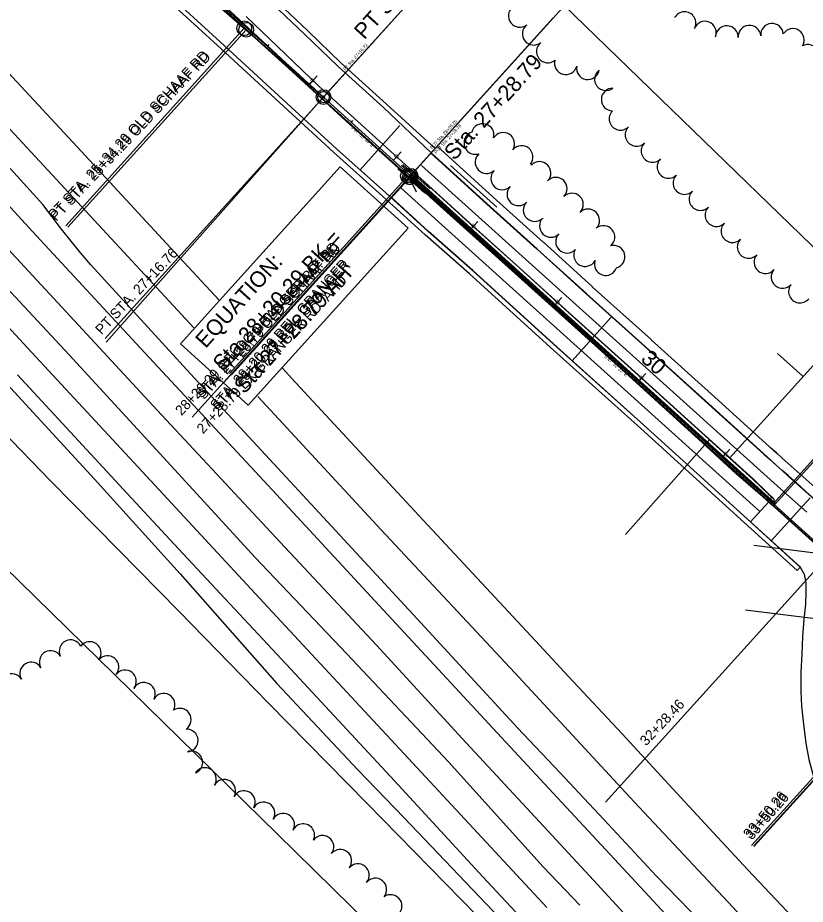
# Model space of a CAD drawing. Extents: x -25029 to 2274964, y -81170 to 687028.
# Drawn here: x -14288 to -13593, y -65698 to -64915 of the extents above; entities that cross this region are included whole.
import ezdxf

# ---------------------------------------------------------------- set-up
doc = ezdxf.new("R2010")
doc.units = 0
for name, color, linetype in [('81911BEA - RW_X_Fee_RW', 7, 'Continuous'), ('BD_P_Building', 7, 'Continuous'), ('BD_X_Canopy', 7, 'Continuous'), ('GE_X_CL_100', 7, 'Continuous'), ('GE_X_CL_20', 7, 'Continuous'), ('GE_X_CL_2000', 7, 'Continuous'), ('GK_Visualization', 7, 'Continuous'), ('INTERSTATE', 7, 'Continuous'), ('MT_P_Edge_Line', 7, 'Continuous'), ('MT_P_Lane_Line', 7, 'Continuous'), ('PM_P_Dotted_Line', 7, 'Continuous'), ('PM_P_Lane_Line', 7, 'Continuous'), ('PM_P_Stop_Line', 7, 'Continuous'), ('PV_X_EOP', 7, 'Continuous'), ('SC_Scratch18', 7, 'Continuous'), ('SC_Scratch19', 7, 'Continuous'), ('SC_Scratch20', 7, 'Continuous'), ('TREES', 7, 'Continuous')]:
    doc.layers.add(name, color=color, linetype=linetype)

msp = doc.modelspace()

# ---------------------------------------------------------------- linework, layer by layer
at = {"layer": '81911BEA - RW_X_Fee_RW'}
msp.add_line((-14059.38, -65635.72), (-13976.56, -65716.81), dxfattribs=at)
for points in [[(-13825.56, -64885.15), (-13539.44, -65162.6), (-13534.78, -65167.2)], [(-14520.82, -65183.95), (-14454.75, -65248.86), (-14188.94, -65508.88), (-14059.38, -65635.72)]]:
    msp.add_lwpolyline(points, dxfattribs=at)
at = {"layer": 'BD_P_Building'}
for p, q in [((-14154.25, -64867.25), (-14018.38, -64985.31)), ((-13937.46, -65056.39), (-13949.55, -65045.59)), ((-13948.22, -65044.94), (-13924.3, -65066.32)), ((-13952.89, -65048.79), (-13928.97, -65070.16)), ((-13939.45, -65058.63), (-13951.55, -65047.83)), ((-13942.8, -65056.23), (-13936.68, -65068.93)), ((-13940.93, -65059.47), (-13936.95, -65055.02))]:
    msp.add_line(p, q, dxfattribs=at)
at = {"layer": 'BD_X_Canopy'}
for p, q in [((-13941.57, -65054.73), (-13643.33, -64724.97)), ((-14018.38, -64985.31), (-13849.38, -64798.31)), ((-14018.38, -64985.31), (-14151.97, -64864.58)), ((-13621.39, -65344.31), (-13323.15, -65014.55)), ((-13620.28, -65345.31), (-13322.04, -65015.56))]:
    msp.add_line(p, q, dxfattribs=at)
msp.add_circle((-13621.39, -65344.31), 1.5, dxfattribs=at)
at = {"layer": 'GE_X_CL_100'}
for p, q in [((-14015.03, -64981.6), (-13855.1, -64804.64)), ((-13938.22, -65051.02), (-13815.56, -64915.39)), ((-14030.77, -64974.08), (-14024.04, -64966.68)), ((-14018.38, -64985.31), (-13941.57, -65054.73)), ((-13956.6, -65041.15), (-13949.89, -65033.73)), ((-14003.55, -65046.87), (-14110.15, -65164.82)), ((-14003.55, -65046.87), (-13943.59, -65101.06)), ((-13941.57, -65054.73), (-13570.99, -65389.89)), ((-13944.92, -65058.44), (-14106.73, -65237.46)), ((-13943.59, -65101.06), (-14084.79, -65257.29)), ((-13888.76, -65102.49), (-13882.05, -65095.08)), ((-13814.59, -65169.57), (-13807.88, -65162.15)), ((-14110.15, -65164.82), (-14144.74, -65203.1)), ((-14084.79, -65257.29), (-14144.74, -65203.1)), ((-13740.43, -65236.65), (-13733.72, -65229.23)), ((-13666.26, -65303.73), (-13659.55, -65296.31))]:
    msp.add_line(p, q, dxfattribs=at)
for centre in [(-14018.38, -64985.31), (-13941.57, -65054.73), (-13941.57, -65054.73)]:
    msp.add_circle(centre, 5, dxfattribs=at)
msp.add_arc((-10176.62, -60734.52), 5729.6, 224.293467, 227.893467, dxfattribs=at)
at = {"layer": 'GE_X_CL_20'}
for p, q in [((-14088.34, -64924.61), (-14245.86, -65098.99)), ((-14088.34, -64924.61), (-12952.92, -65950.25)), ((-14017.71, -64984.57), (-13973.41, -64935.55)), ((-14067.62, -64940.28), (-14066.26, -64938.82)), ((-14030.77, -64974.08), (-14029.43, -64972.6)), ((-14018.38, -64985.31), (-14211.12, -65198.57)), ((-14019.51, -64986.7), (-14210.21, -65201.8)), ((-14018.38, -64985.31), (-13941.57, -65054.73)), ((-13993.69, -65007.62), (-13992.35, -65006.14)), ((-13941.57, -65054.73), (-13893.63, -65001.68)), ((-13940.9, -65053.99), (-13893.83, -65001.94)), ((-13956.6, -65041.15), (-13955.26, -65039.66)), ((-13941.57, -65054.73), (-14134.32, -65267.99)), ((-13941.57, -65054.73), (-13570.99, -65389.89)), ((-13940.9, -65053.99), (-13619.61, -65344.57)), ((-13940.57, -65053.61), (-13619.27, -65344.2)), ((-13944, -65054.99), (-14101.52, -65229.37)), ((-13942.58, -65055.84), (-13621.28, -65346.43)), ((-13942.24, -65055.47), (-13620.95, -65346.06)), ((-13925.84, -65068.95), (-13924.5, -65067.47)), ((-13888.76, -65102.49), (-13887.42, -65101.01)), ((-13851.68, -65136.03), (-13850.33, -65134.55)), ((-13814.59, -65169.57), (-13813.25, -65168.09)), ((-13777.51, -65203.11), (-13776.17, -65201.63)), ((-13740.43, -65236.65), (-13739.09, -65235.17)), ((-13703.34, -65270.19), (-13702, -65268.7)), ((-13666.26, -65303.73), (-13664.92, -65302.24)), ((-13629.18, -65337.26), (-13627.84, -65335.78)), ((-13482.83, -65471.57), (-13640.35, -65645.95))]:
    msp.add_line(p, q, dxfattribs=at)
for centre, radius in [((-14088.34, -64924.61), 6.46), ((-14018.38, -64985.31), 6.46), ((-14018.38, -64985.31), 1), ((-13944, -65054.99), 6.46), ((-13941.57, -65054.73), 6.46), ((-13941.57, -65054.73), 1), ((-13941.57, -65054.73), 1)]:
    msp.add_circle(centre, radius, dxfattribs=at)
msp.add_arc((-10176.62, -60734.52), 5729.6, 224.293467, 227.893467, dxfattribs=at)
at = {"layer": 'GE_X_CL_2000'}
for points in [[(-14110.55, -65164.51), (-14149.64, -65122.46), (-14232.38, -65033.07), (-14331.2, -64926.77), (-14435.97, -64813.68), (-14530.31, -64711.32), (-14629.05, -64601.39), (-14673.9, -64549.55)], [(-14795.36, -64711.11), (-14635.94, -64875.63), (-14526.42, -64992.05), (-14414.68, -65111.67), (-14390.89, -65138.08), (-14315.48, -65219.95), (-14220.65, -65322.6), (-14145.05, -65406.13), (-14059.61, -65503.13), (-13988.06, -65579.37)], [(-13685.3, -65713.53), (-13724.7, -65672.87), (-13766.9, -65627.54), (-13809.75, -65581.55), (-13847.16, -65542.09), (-13935.82, -65445.94), (-14025.68, -65348.41), (-14135.75, -65229.65), (-14223.79, -65133.51), (-14232.65, -65123.17), (-14241.32, -65112.66), (-14249.78, -65101.99), (-14258.04, -65091.16), (-14266.09, -65080.18), (-14314.67, -65026.81)], [(-14322.7, -65127.56), (-14243.01, -65212.95), (-14159.51, -65303.7), (-14078.6, -65391.69), (-13997.83, -65476.78), (-13907.94, -65572.17), (-13824.32, -65664.78), (-13792.21, -65698.78)], [(-13594.69, -65719.67), (-13643.65, -65667.67), (-13677.75, -65630.88), (-13716.89, -65588.49), (-13754.7, -65547.56), (-13802.06, -65496.9), (-13831.12, -65465.44), (-13847.06, -65448.29), (-13934.21, -65354.59), (-14046.25, -65233.68), (-14054.73, -65224.56)], [(-13988.06, -65579.37), (-13947.34, -65621.46), (-13831.97, -65742.31)]]:
    msp.add_lwpolyline(points, dxfattribs=at)
at = {"layer": 'GK_Visualization'}
msp.add_line((-13941.57, -65054.73), (-13570.99, -65389.89), dxfattribs=at)
at = {"layer": 'INTERSTATE'}
msp.add_lwpolyline([(-12958.53, -66453.41), (-13014.05, -66394.29), (-13095.42, -66307.36), (-13172.46, -66224.15), (-13272.06, -66115.98), (-13357.27, -66023.46), (-13436.17, -65938.98), (-13503.35, -65866.48), (-13579.97, -65783.79), (-13657.09, -65700.57), (-13744.1, -65607.44), (-13849.48, -65493.49), (-13967.79, -65367.02), (-14065.28, -65261.64), (-14076.45, -65249.65)], dxfattribs=at)
at = {"layer": 'MT_P_Edge_Line'}
for p, q in [((-13923.59, -65034.84), (-13874.05, -65079.87)), ((-13938.68, -65051.53), (-13889.19, -65096.52)), ((-13874.14, -65079.79), (-13829.9, -65119.58)), ((-13889.19, -65096.52), (-13844.95, -65136.31)), ((-13829.82, -65119.66), (-13786.44, -65159.07)), ((-13844.95, -65136.31), (-13801.57, -65175.72)), ((-13786.54, -65158.97), (-13734.58, -65205.59)), ((-13801.57, -65175.72), (-13749.61, -65222.34)), ((-13734.55, -65205.62), (-13675.48, -65259.1)), ((-13749.61, -65222.34), (-13690.58, -65275.78)), ((-13675.48, -65259.1), (-13623.39, -65306.26)), ((-13690.58, -65275.78), (-13638.77, -65322.69)), ((-13653.94, -65317.86), (-13684.09, -65290.41)), ((-13624.44, -65343.42), (-13653.94, -65317.86)), ((-13638.76, -65322.69), (-13625.69, -65335.28)), ((-13625.7, -65335.28), (-13621.24, -65339.31))]:
    msp.add_line(p, q, dxfattribs=at)
for points in [[(-13684.09, -65290.41), (-13758.11, -65222.95), (-13843.55, -65145.98), (-13920.85, -65076.49), (-13943.14, -65056.46)], [(-13597.23, -65400.22), (-13653.64, -65349.08), (-13735.8, -65274.57), (-13812.47, -65205.68), (-13886.63, -65138.29), (-13925.73, -65103.9), (-13958.7, -65073.82)]]:
    msp.add_lwpolyline(points, dxfattribs=at)
msp.add_lwpolyline([(-13622.41, -65338.59), (-13625.64, -65342.19), (-13624.77, -65342.98), (-13624.17, -65343.48), (-13623.55, -65343.75), (-13623.03, -65343.85), (-13622.28, -65343.79), (-13621.69, -65343.59), (-13621.01, -65343.05), (-13620.66, -65342.46), (-13620.49, -65341.73), (-13620.44, -65341.22), (-13620.6, -65340.49), (-13621.12, -65339.76), (-13621.81, -65339.13)], close=True, dxfattribs=at)
msp.add_arc((-23716.78, -76654.7), 15187.62, 47.53132, 48.379524, dxfattribs=at)
at = {"layer": 'MT_P_Lane_Line'}
for p, q in [((-13614.85, -65331.12), (-13931.78, -65045.59)), ((-13633.01, -65351.28), (-13949.94, -65065.75))]:
    msp.add_line(p, q, dxfattribs=at)
at = {"layer": 'PM_P_Dotted_Line'}
msp.add_line((-13614.85, -65331.12), (-13591.77, -65351.92), dxfattribs=at)
at = {"layer": 'PM_P_Lane_Line'}
msp.add_line((-13906.15, -65045.79), (-13865.46, -65082.49), dxfattribs=at)
at = {"layer": 'PM_P_Stop_Line'}
for p, q in [((-14086.57, -64925.86), (-14244.05, -65100.27)), ((-14086.57, -64925.86), (-12950.89, -65951.2)), ((-13942.21, -65056.2), (-14099.68, -65230.62)), ((-13641.25, -65360.31), (-13625.38, -65342.81)), ((-13480.93, -65472.66), (-13638.4, -65647.08))]:
    msp.add_line(p, q, dxfattribs=at)
for centre in [(-14086.57, -64925.86), (-13942.21, -65056.2)]:
    msp.add_circle(centre, 6.46, dxfattribs=at)
at = {"layer": 'PV_X_EOP'}
for p, q in [((-14069.47, -64897), (-14035.09, -64929.81)), ((-14066.71, -64894.11), (-14032.33, -64926.92)), ((-14086.66, -64914.3), (-14051.95, -64947.43)), ((-14032.33, -64926.92), (-14002.75, -64955.29)), ((-14035.09, -64929.81), (-14005.48, -64958.21)), ((-14051.95, -64947.43), (-14022.12, -64976.04)), ((-14005.48, -64958.21), (-13965.52, -64994.5)), ((-14002.75, -64955.29), (-13962.83, -64991.54)), ((-14022.12, -64976.04), (-13981.92, -65012.55)), ((-13962.83, -64991.54), (-13919.81, -65030.66)), ((-13965.52, -64994.5), (-13923.42, -65034.66)), ((-13981.92, -65012.55), (-13939.88, -65050.77)), ((-13919.81, -65030.66), (-13917.12, -65027.69)), ((-13918.05, -65028.72), (-13868.5, -65073.77)), ((-13923.42, -65034.66), (-13873.88, -65079.69)), ((-13939.88, -65050.77), (-13889.35, -65096.7)), ((-13868.62, -65073.66), (-13824.38, -65113.45)), ((-13873.97, -65079.6), (-13829.73, -65119.39)), ((-13889.35, -65096.7), (-13845.11, -65136.49)), ((-13824.27, -65113.55), (-13780.89, -65152.96)), ((-13829.65, -65119.47), (-13786.27, -65158.88)), ((-13845.11, -65136.49), (-13801.73, -65175.9)), ((-13781.03, -65152.83), (-13729.07, -65199.45)), ((-13786.38, -65158.79), (-13734.42, -65205.41)), ((-13801.73, -65175.9), (-13749.77, -65222.52)), ((-13729.01, -65199.51), (-13669.94, -65252.99)), ((-13734.38, -65205.44), (-13675.31, -65258.92)), ((-13749.77, -65222.52), (-13690.74, -65275.96)), ((-13669.94, -65252.99), (-13617.85, -65300.15)), ((-13675.31, -65258.92), (-13623.22, -65306.08)), ((-13690.74, -65275.96), (-13638.93, -65322.87)), ((-13653.77, -65317.67), (-13683.92, -65290.22)), ((-13629.4, -65338.78), (-13653.77, -65317.67)), ((-13638.93, -65322.87), (-13625.86, -65335.46)), ((-13625.86, -65335.46), (-13621.41, -65339.49)), ((-13629.11, -65339.05), (-13624.57, -65343.16)), ((-13625.66, -65342.17), (-13622.41, -65338.59)), ((-13600.08, -65403.37), (-13597.39, -65400.4))]:
    msp.add_line(p, q, dxfattribs=at)
for points in [[(-13683.92, -65290.22), (-13757.94, -65222.76), (-13843.38, -65145.79), (-13920.68, -65076.3), (-13998.33, -65006.52), (-14079.27, -64932.04), (-14137.65, -64878.69), (-14184.85, -64835.65), (-14226.85, -64795.7), (-14257.17, -64766.5), (-14286.36, -64738.29)], [(-14132.84, -65189.05), (-14169.13, -65150.03), (-14235.6, -65078.13), (-14347.41, -64957.67), (-14462.09, -64833.67), (-14539.76, -64748.36)], [(-13600.08, -65403.37), (-13656.49, -65352.23), (-13738.64, -65277.72), (-13815.32, -65208.83), (-13889.46, -65141.46), (-13928.56, -65107.06), (-13966.15, -65072.77), (-14009.69, -65033.87), (-14112.38, -64939.55), (-14179.37, -64878.13), (-14309.3, -64760.68)], [(-13597.39, -65400.4), (-13653.8, -65349.26), (-13735.96, -65274.75), (-13812.63, -65205.86), (-13886.79, -65138.47), (-13925.89, -65104.08), (-13963.46, -65069.8), (-14007, -65030.9), (-14054.34, -64987.42), (-14109.67, -64936.6), (-14176.67, -64875.17), (-14306.43, -64757.88)], [(-14382.02, -64987.79), (-14275.46, -65104.01), (-14176.28, -65211.24), (-14063.55, -65332.3), (-13969.16, -65434.21), (-13850.1, -65562.87), (-13730.89, -65691.03), (-13604.15, -65828.11)], [(-14389.94, -65087.43), (-14279.9, -65206.41), (-14185.93, -65307.8), (-14067.43, -65435.51), (-13943.29, -65569.27), (-13821.19, -65700.9)], [(-13736.37, -65724.08), (-13779.99, -65676.71), (-13827.64, -65625.13), (-13895.81, -65551.53), (-13971.72, -65469.21), (-14056.68, -65378.22), (-14165.19, -65261.74), (-14300.6, -65115.56)], [(-13783.32, -65774.94), (-13877.59, -65673.83), (-13959.13, -65585.16), (-14051.34, -65485.91), (-14146.32, -65384.27), (-14195.3, -65331.45), (-14288.49, -65230.42)], [(-14302.52, -65279.75), (-14259.12, -65324.36), (-14199.82, -65384.68), (-14146.24, -65439.14), (-14067.33, -65520.01), (-13979.86, -65608.96), (-13869.11, -65721.96)], [(-13597.39, -65400.4), (-13593.92, -65406.41), (-13592.44, -65414.47), (-13592.51, -65423.21), (-13592.74, -65432.97), (-13594.29, -65446.66), (-13595.43, -65461.46), (-13596.08, -65476.76), (-13596.98, -65493.37), (-13596.86, -65510), (-13596.38, -65523.09), (-13594.66, -65539.04), (-13592.6, -65555.86), (-13589.75, -65570.09), (-13586.3, -65582.97), (-13582.48, -65598.89), (-13577.2, -65614.12), (-13570.86, -65630.39), (-13564.04, -65647.76), (-13556.86, -65661.88), (-13550.9, -65672.79), (-13538.17, -65693.91), (-13517.19, -65723.89)]]:
    msp.add_lwpolyline(points, dxfattribs=at)
for centre, radius, start, end in [((-23716.78, -76654.7), 15195.87, 47.53132, 48.379524), ((-23716.78, -76654.7), 15187.87, 47.53132, 48.379524), ((-13622.87, -65341.43), 2.42, 225.62221, 52.87799)]:
    msp.add_arc(centre, radius, start, end, dxfattribs=at)
at = {"layer": 'SC_Scratch18'}
for p, q in [((-14099.56, -65229.76), (-13942.04, -65055.38)), ((-13535.88, -65166.7), (-13659.89, -65303.98)), ((-13594.93, -65232.08), (-13617.55, -65211.65)), ((-13638.17, -65323.6), (-13659.89, -65303.98)), ((-13572.14, -65389.52), (-13638.48, -65381.14)), ((-13572.14, -65389.52), (-13769.32, -65607.82)), ((-13579.34, -65446.56), (-13645.68, -65438.18)), ((-13480.87, -65471.97), (-13638.39, -65646.35))]:
    msp.add_line(p, q, dxfattribs=at)
at = {"layer": 'SC_Scratch19'}
for p, q in [((-13986.04, -65049.64), (-13951.1, -65010.53)), ((-13798.95, -65218.16), (-13764.4, -65179.71)), ((-13623.16, -65377.04), (-13588.81, -65339.15))]:
    msp.add_line(p, q, dxfattribs=at)
at = {"layer": 'SC_Scratch20'}
msp.add_line((-13751.78, -65371.43), (-13677.26, -65287.37), dxfattribs=at)
at = {"layer": 'TREES'}
for centre, radius, start, end in [((-13845.17, -64913.65), 10, 128.0554, 308.0554), ((-13699.67, -64920.02), 10, 330.97573, 150.97573), ((-13832.84, -64929.4), 10, 128.0554, 308.0554), ((-13681.58, -64928.44), 10, 339.10886, 159.10886), ((-13622.36, -64930.34), 10, 4.74539, 184.74539), ((-13662.25, -64932.41), 10, 357.63981, 177.63981), ((-13642.29, -64932), 10, 4.74539, 184.74539), ((-13603.94, -64934.86), 10, 327.67715, 147.67715), ((-13820.4, -64945.06), 10, 128.86068, 308.86068), ((-13590.68, -64948.98), 10, 298.75409, 118.75409), ((-13804.47, -64955.45), 10, 164.93591, 344.93591), ((-13784.97, -64959.84), 10, 169.6971, 349.6971), ((-13769.02, -64969.54), 10, 127.68861, 307.68861), ((-13763.06, -64987.45), 10, 89.12973, 269.12973), ((-13756.15, -65004.53), 10, 134.89263, 314.89263), ((-13877.85, -65018.86), 10, 345.6231, 165.6231), ((-13742.04, -65018.7), 10, 134.89263, 314.89263), ((-13884.34, -65025.85), 10, 108.64062, 288.64062), ((-13859.67, -65026.63), 10, 328.09303, 148.09303), ((-13843.44, -65038.24), 10, 320.76427, 140.76427), ((-13727.92, -65032.87), 10, 134.89263, 314.89263), ((-13874.46, -65042.77), 10, 131.94653, 311.94653), ((-13835.24, -65044.93), 0.58, 320.76427, 140.76427), ((-13827.64, -65052.28), 10, 315.71834, 135.71834), ((-13713.81, -65047.04), 10, 134.89263, 314.89263), ((-13860.62, -65057.19), 10, 135.72102, 315.72102), ((-13699.69, -65061.21), 10, 134.89263, 314.89263), ((-13813.32, -65066.24), 10, 315.71834, 135.71834), ((-13846.3, -65071.15), 10, 135.72102, 315.72102), ((-13799, -65080.21), 10, 315.71834, 135.71834), ((-13685.58, -65075.38), 10, 134.89263, 314.89263), ((-13831.98, -65085.11), 10, 135.72102, 315.72102), ((-13784.68, -65094.17), 10, 315.71834, 135.71834), ((-13671.46, -65089.55), 10, 134.89263, 314.89263), ((-13817.66, -65099.08), 10, 135.72102, 315.72102), ((-13771.18, -65108.88), 10, 309.37052, 129.37052), ((-13657.35, -65103.71), 10, 134.89263, 314.89263), ((-13803.34, -65113.04), 10, 135.72102, 315.72102), ((-13762.25, -65126.28), 10, 284.96453, 104.96453), ((-13643.02, -65117.67), 10, 136.58514, 316.58514), ((-13787.42, -65124.85), 10, 151.12183, 331.12183), ((-13628.2, -65131.09), 10, 139.13334, 319.13334), ((-13769.17, -65132.81), 10, 161.767, 341.767), ((-13613.07, -65144.17), 10, 139.13334, 319.13334), ((-13597.75, -65157.02), 10, 140.93004, 320.93004), ((-14241.69, -65474.54), 10, 26.55347, 206.55347), ((-14224.77, -65476.1), 10, 322.89384, 142.89384), ((-14259.26, -65484.08), 10, 30.4665, 210.4665), ((-14276.49, -65494.22), 10, 30.4665, 210.4665), ((-14209.12, -65488.55), 10, 320.0955, 140.0955), ((-14193.63, -65501.19), 10, 321.49166, 141.49166), ((-14293.73, -65504.36), 10, 30.4665, 210.4665), ((-14177.01, -65512.18), 10, 331.51598, 151.51597), ((-14159.48, -65521.81), 10, 330.9474, 150.9474), ((-14145.21, -65535), 10, 303.5482, 123.5482), ((-14139.14, -65553.32), 10, 273.1311, 93.1311), ((-14135.07, -65572.66), 10, 290.61704, 110.61704), ((-14123.1, -65587.37), 10, 327.66218, 147.66218), ((-14106, -65597.73), 10, 329.93278, 149.93278), ((-14088.69, -65607.75), 10, 329.93278, 149.93278), ((-14071.38, -65617.77), 10, 329.93278, 149.93278), ((-14053.99, -65627.65), 10, 330.85996, 150.85996), ((-14036.27, -65636.9), 10, 334.02588, 154.02588), ((-14019.26, -65647.25), 10, 323.35416, 143.35416), ((-14003.5, -65659.56), 10, 320.64519, 140.64519), ((-13988.04, -65672.24), 10, 320.64519, 140.64519), ((-13972.58, -65684.93), 10, 320.6062, 140.6062), ((-13959.16, -65699.5), 10, 304.67094, 124.67094)]:
    msp.add_arc(centre, radius, start, end, dxfattribs=at)

# ---------------------------------------------------------------- texts
at = {"layer": 'GE_X_CL_100'}
for s, rotation, p in [('PT Sta. 27+16.72', 47.89347, (-13982.31, -64935.28)), ('Sta. 27+28.79', 47.8729, (-13902.85, -65042.05)), ('Sta 28+20.29 BK = ', 47.89347, (-14107.08, -65228.2)), ('EQUATION:', 47.89347, (-14122.49, -65207.81)), ('Sta 27+28.79 AH', 47.89347, (-14088.36, -65248.18)), ('30', 317.8729, (-13739.07, -65217.65))]:
    msp.add_text(s, height=14, rotation=rotation, dxfattribs=at).set_placement(p)
at = {"layer": 'GE_X_CL_20'}
for s, height, rotation, p in [('PT STA. 25+34.29 OLD SCHAAF RD', 8.96, 46.58623, (-14256.02, -65094.16)), ('PT Sta. 27+16.72', 2.8, 47.89347, (-13999.3, -64962.11)), ('27', 2.8, 317.72625, (-14030.47, -64970.29)), ('POT Sta. 28+20.25', 2.8, 47.89347, (-13922.5, -65031.53)), ('S 47%%d 53\' 36" E', 2.8, 317.89347, (-13994.73, -65012.34)), ('POT Sta. 27+28.79', 2.8, 47.8729, (-13918.78, -65035.49)), ('28', 2.8, 317.89347, (-13956.22, -65037.44)), ('28', 2.8, 317.8729, (-13888.38, -65098.79)), ('28+20.29 RELOC GRANGER RD. BK', 8.96, 46.58623, (-14143.75, -65267.08)), ('STA. 27+28.79 OLD SCHAAF RD', 8.96, 47.71016, (-14125.85, -65251.75)), ('PT STA. 27+16.76', 8.96, 46.58623, (-14214.31, -65195.67)), ('STA. 28+20.29 REL. GRANGER', 8.96, 47.71016, (-14112.78, -65262.2)), ('27+28.79 EX GRANGER RD. AHD', 8.96, 46.58623, (-14124.77, -65283.14)), ('29', 2.8, 317.8729, (-13814.25, -65165.84)), ('S 47%%d 52\' 22" E', 2.8, 317.8729, (-13770.93, -65214.72)), ('30', 2.8, 317.8729, (-13740.16, -65232.85)), ('31', 2.8, 317.8729, (-13665.6, -65300.28)), ('33+50.26', 8.96, 48.58521, (-13641.99, -65640.66))]:
    msp.add_text(s, height=height, rotation=rotation, dxfattribs=at).set_placement(p)
at = {"layer": 'PM_P_Stop_Line'}
for s, rotation, p in [('PT STA. 25+34.29 OLD SCHAAF RD', 46.60093, (-14254.21, -65095.45)), ('STA. 27+28.79 OLD SCHAAF RD', 47.72486, (-14124, -65253)), ('STA. 28+20.29 REL. GRANGER', 47.72486, (-14110.93, -65263.45)), ('33+50.26', 48.59991, (-13640.05, -65641.79))]:
    msp.add_text(s, height=8.96, rotation=rotation, dxfattribs=at).set_placement(p)
at = {"layer": 'SC_Scratch18'}
msp.add_text('32+28.46', height=8.96, rotation=46.58623, dxfattribs=at).set_placement((-13733.47, -65558.61))

doc.saveas('drawing.dxf')
